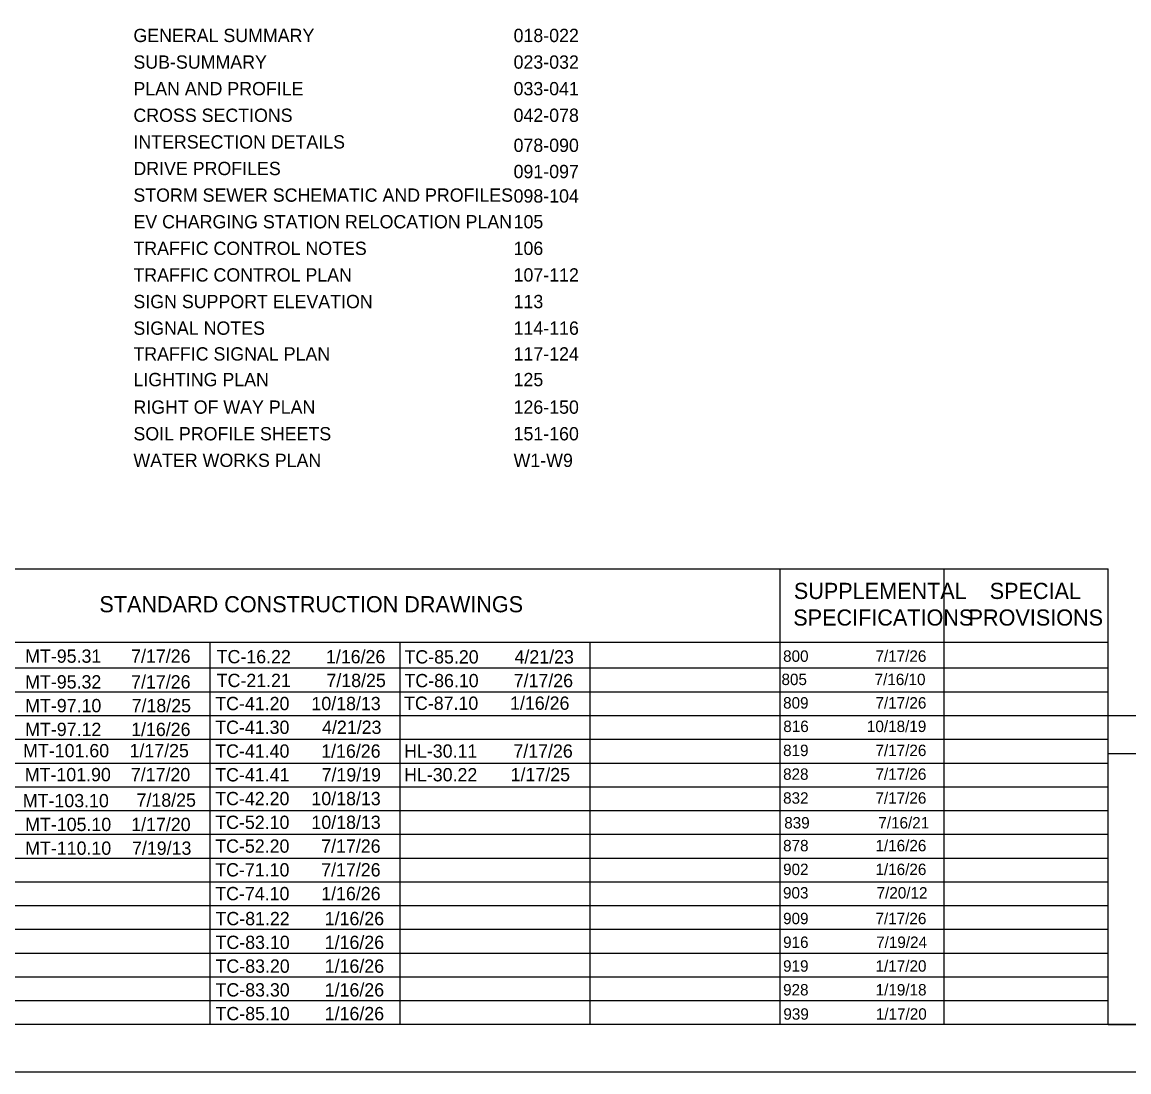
# Model space of a CAD drawing. Extents: x 0 to 34, y -3.9 to 26.2.
# Drawn here: x 12.17 to 23.82, y 0 to 11.05 of the extents above; entities that cross this region are included whole.
import ezdxf

# ---------------------------------------------------------------- set-up
doc = ezdxf.new("R2010")
doc.units = 0
for name, color, linetype in [('SH_Border', 7, 'Continuous'), ('SH_Cut_Line', 7, 'Continuous'), ('SH_Data', 7, 'Continuous'), ('SH_Text', 7, 'Continuous')]:
    doc.layers.add(name, color=color, linetype=linetype)

msp = doc.modelspace()

# ---------------------------------------------------------------- linework, layer by layer
at = {"layer": 'SH_Border'}
msp.add_lwpolyline([(1.5, 21.5), (33.5, 21.5), (33.5, 0.5), (1.5, 0.5)], close=True, dxfattribs=at)
at = {"layer": 'SH_Cut_Line'}
msp.add_lwpolyline([(0, 0), (34, 0), (34, 22), (0, 22)], close=True, dxfattribs=at)
at = {"layer": 'SH_Data'}
for p, q in [((10.15, 5.292), (23.6, 5.292)), ((20.15, 0.5), (20.15, 5.292)), ((21.875, 0.5), (21.875, 5.292)), ((23.6, 0.5), (23.6, 5.292)), ((10.15, 4.521), (23.6, 4.521)), ((14.15, 0.5), (14.15, 4.521)), ((16.15, 0.5), (16.15, 4.521)), ((18.15, 0.5), (18.15, 4.521)), ((10.15, 4.25), (23.6, 4.25)), ((10.15, 4), (23.6, 4)), ((10.15, 3.75), (23.6, 3.75)), ((23.6, 0.5), (23.6, 3.75)), ((23.6, 3.75), (26.4, 3.75)), ((10.15, 3.5), (23.6, 3.5)), ((23.6, 3.35), (26.4, 3.35)), ((10.15, 3.25), (23.6, 3.25)), ((10.15, 3), (23.6, 3)), ((10.15, 2.75), (23.6, 2.75)), ((10.15, 2.5), (23.6, 2.5)), ((10.15, 2.25), (23.6, 2.25)), ((10.15, 2), (23.6, 2)), ((10.15, 1.75), (23.6, 1.75)), ((10.15, 1.5), (23.6, 1.5)), ((10.15, 1.25), (23.6, 1.25)), ((10.15, 1), (23.6, 1)), ((10.15, 0.75), (23.6, 0.75)), ((23.6, 0.5), (26.4, 0.5))]:
    msp.add_line(p, q, dxfattribs=at)

# ---------------------------------------------------------------- texts
at = {"layer": 'SH_Text'}
for s, height, p in [('GENERAL SUMMARY', 0.14, (13.344, 10.836)), ('018-022', 0.14, (17.344, 10.836)), ('SUB-SUMMARY', 0.14, (13.344, 10.556)), ('023-032', 0.14, (17.344, 10.556)), ('PLAN AND PROFILE', 0.14, (13.344, 10.276)), ('033-041', 0.14, (17.344, 10.276)), ('CROSS SECTIONS', 0.14, (13.344, 9.996)), ('042-078', 0.14, (17.344, 9.996)), ('INTERSECTION DETAILS', 0.14, (13.344, 9.716)), ('078-090', 0.14, (17.344, 9.68)), ('DRIVE PROFILES', 0.14, (13.344, 9.436)), ('091-097', 0.14, (17.344, 9.404)), ('STORM SEWER SCHEMATIC AND PROFILES', 0.14, (13.344, 9.156)), ('098-104', 0.14, (17.344, 9.147)), ('EV CHARGING STATION RELOCATION PLAN', 0.14, (13.344, 8.876)), ('105', 0.14, (17.344, 8.876)), ('TRAFFIC CONTROL NOTES', 0.14, (13.344, 8.596)), ('106', 0.14, (17.344, 8.596)), ('TRAFFIC CONTROL PLAN', 0.14, (13.344, 8.316)), ('107-112', 0.14, (17.344, 8.316)), ('SIGN SUPPORT ELEVATION', 0.14, (13.344, 8.036)), ('113', 0.14, (17.344, 8.036)), ('SIGNAL NOTES', 0.14, (13.344, 7.756)), ('114-116', 0.14, (17.344, 7.756)), ('TRAFFIC SIGNAL PLAN', 0.14, (13.344, 7.485)), ('117-124', 0.14, (17.344, 7.485)), ('LIGHTING PLAN', 0.14, (13.344, 7.215)), ('125', 0.14, (17.344, 7.215)), ('RIGHT OF WAY PLAN', 0.14, (13.344, 6.925)), ('126-150', 0.14, (17.344, 6.925)), ('SOIL PROFILE SHEETS', 0.14, (13.344, 6.645)), ('151-160', 0.14, (17.344, 6.645)), ('WATER WORKS PLAN', 0.14, (13.344, 6.365)), ('W1-W9', 0.14, (17.344, 6.365)), ('SUPPLEMENTAL', 0.17, (20.293, 4.976)), ('SPECIAL', 0.17, (22.354, 4.976)), ('STANDARD CONSTRUCTION DRAWINGS', 0.17, (12.986, 4.836)), ('SPECIFICATIONS', 0.17, (20.287, 4.696)), ('PROVISIONS', 0.17, (22.132, 4.696)), ('MT-95.31', 0.14, (12.205, 4.305)), ('7/17/26', 0.14, (13.32, 4.305)), ('TC-16.22', 0.14, (14.22, 4.299)), ('1/16/26', 0.14, (15.37, 4.299)), ('TC-85.20', 0.14, (16.196, 4.297)), ('4/21/23', 0.14, (17.354, 4.297)), ('800', 0.12, (20.18, 4.315)), ('7/17/26', 0.12, (21.152, 4.315)), ('7/18/25', 0.14, (15.375, 4.049)), ('7/17/26', 0.14, (17.345, 4.047)), ('7/16/10', 0.12, (21.143, 4.07)), ('MT-95.32', 0.14, (12.205, 4.034)), ('7/17/26', 0.14, (13.32, 4.034)), ('TC-21.21', 0.14, (14.22, 4.049)), ('TC-86.10', 0.14, (16.196, 4.047)), ('805', 0.12, (20.163, 4.07)), ('MT-97.10', 0.14, (12.205, 3.784)), ('7/18/25', 0.14, (13.325, 3.784)), ('TC-41.20', 0.14, (14.205, 3.806)), ('10/18/13', 0.14, (15.217, 3.806)), ('TC-87.10', 0.14, (16.192, 3.809)), ('1/16/26', 0.14, (17.307, 3.81)), ('809', 0.12, (20.18, 3.823)), ('7/17/26', 0.12, (21.152, 3.823)), ('MT-97.12', 0.14, (12.205, 3.534)), ('1/16/26', 0.14, (13.32, 3.534)), ('TC-41.30', 0.14, (14.205, 3.556)), ('4/21/23', 0.14, (15.329, 3.556)), ('816', 0.12, (20.182, 3.576)), ('10/18/19', 0.12, (21.062, 3.576)), ('MT-101.60', 0.14, (12.183, 3.31)), ('1/17/25', 0.14, (13.303, 3.31)), ('TC-41.40', 0.14, (14.205, 3.306)), ('1/16/26', 0.14, (15.32, 3.306)), ('HL-30.11', 0.14, (16.192, 3.306)), ('7/17/26', 0.14, (17.342, 3.306)), ('819', 0.12, (20.18, 3.323)), ('7/17/26', 0.12, (21.152, 3.323)), ('MT-101.90', 0.14, (12.201, 3.058)), ('7/17/20', 0.14, (13.317, 3.058)), ('TC-41.41', 0.14, (14.205, 3.056)), ('7/19/19', 0.14, (15.324, 3.056)), ('HL-30.22', 0.14, (16.192, 3.057)), ('1/17/25', 0.14, (17.313, 3.058)), ('828', 0.12, (20.18, 3.073)), ('7/17/26', 0.12, (21.152, 3.073)), ('MT-103.10', 0.14, (12.18, 2.784)), ('7/18/25', 0.14, (13.377, 2.79)), ('TC-42.20', 0.14, (14.205, 2.806)), ('10/18/13', 0.14, (15.217, 2.806)), ('832', 0.12, (20.18, 2.822)), ('7/17/26', 0.12, (21.152, 2.822)), ('1/17/20', 0.14, (13.321, 2.534)), ('TC-52.10', 0.14, (14.205, 2.556)), ('10/18/13', 0.14, (15.217, 2.556)), ('839', 0.12, (20.192, 2.561)), ('7/16/21', 0.12, (21.182, 2.561)), ('MT-105.10', 0.14, (12.205, 2.534)), ('TC-52.20', 0.14, (14.205, 2.306)), ('7/17/26', 0.14, (15.32, 2.306)), ('1/16/26', 0.12, (21.152, 2.321)), ('MT-110.10', 0.14, (12.205, 2.284)), ('7/19/13', 0.14, (13.329, 2.284)), ('878', 0.12, (20.18, 2.321)), ('TC-71.10', 0.14, (14.205, 2.056)), ('7/17/26', 0.14, (15.32, 2.056)), ('902', 0.12, (20.18, 2.071)), ('1/16/26', 0.12, (21.152, 2.071)), ('TC-74.10', 0.14, (14.205, 1.806)), ('1/16/26', 0.14, (15.32, 1.806)), ('903', 0.12, (20.179, 1.824)), ('7/20/12', 0.12, (21.164, 1.824)), ('TC-81.22', 0.14, (14.208, 1.543)), ('1/16/26', 0.14, (15.357, 1.543)), ('909', 0.12, (20.18, 1.554)), ('7/17/26', 0.12, (21.152, 1.554)), ('TC-83.10', 0.14, (14.208, 1.293)), ('1/16/26', 0.14, (15.357, 1.293)), ('916', 0.12, (20.18, 1.304)), ('7/19/24', 0.12, (21.159, 1.304)), ('TC-83.20', 0.14, (14.208, 1.043)), ('1/16/26', 0.14, (15.357, 1.043)), ('919', 0.12, (20.18, 1.054)), ('1/17/20', 0.12, (21.153, 1.054)), ('TC-83.30', 0.14, (14.208, 0.793)), ('1/16/26', 0.14, (15.357, 0.793)), ('928', 0.12, (20.18, 0.804)), ('1/19/18', 0.12, (21.154, 0.804)), ('TC-85.10', 0.14, (14.208, 0.543)), ('1/16/26', 0.14, (15.357, 0.543)), ('939', 0.12, (20.183, 0.549)), ('1/17/20', 0.12, (21.156, 0.549))]:
    msp.add_text(s, height=height, dxfattribs=at).set_placement(p)

doc.saveas('drawing.dxf')
